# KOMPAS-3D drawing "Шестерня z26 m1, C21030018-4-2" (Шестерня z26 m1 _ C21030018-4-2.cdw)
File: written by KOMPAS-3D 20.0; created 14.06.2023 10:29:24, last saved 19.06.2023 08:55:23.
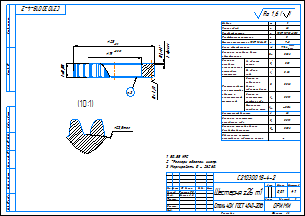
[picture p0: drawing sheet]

Sheet 1: A3, landscape

Document properties: Автор: user; Полное имя файла: C:\Users\kosenko.ky\Desktop\Чертежи\6 Июнь 2023\17. Шестерня z26 m1 _ C21030018-4-2\Шестерня z26 m1 _ C21030018-4-2.cdw; Знак неуказанной шероховатости: 4; Параметр неуказанной шероховатости: Ra 1,6; Масса: 0.00931038

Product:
- Part/product: Шестерня z26 m1  | designation C21030018-4-2
    Материал: Сталь 40Х  ГОСТ 4543-2016 (density 7850 kg/m3)
    Масса: 0.00931038
    source file: Шестерня z26 m1 _ C21030018-4-2.cdw

Title block, sheet 1: Наименование: Шестерня z26 m1; designation: C21030018-4-2; Материал: Сталь 40Х  ГОСТ 4543-2016; Масса: 0,01; Количество листов документа: 1; organisation: ОРИМИ; Форматы листов документа: A3; stored path: C:\Users\kosenko.ky\Desktop\Шестерня z26 m1 _ C21030018-4-2.cdw; Разработал: Косенко К.Ю.; Проверил: Михаль А.Д.
Table, sheet 1:
  669581292 / 683438702

Views: Проекционный вид 2, Местный разрез 1
Referenced files: mrsmyb.frw
Referenced files in C:\Users\kosenko.ky\Desktop\: Шестерня z26 m1 _ C21030018-4-2.m3d
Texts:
  Ячейка таблицы
  Ra 1,25
  Обозначение чертежа
  сопряжённого зубчатого колеса
  Допуск на торцовое биение
  базовой поверхности
  Допуск на погрешность
  направления зуба
  Делительный диаметр
  Контролировать
  при отсутствии
  обкатки с
  измерительной
  шестерней
  Допуск на
  колебание
  измерительного
  межосевого
  расстояния
  Допуск на колебание длины
  общей нормали
  Длина общей нормали
  Степень точности по ГОСТ 1643-81
  Коэффициент смещения
  Исходный контур
  Число зубьев
  Модуль
  Отклонение
  основного шага
  погрешность
  профиля зуба
  радиальное
  биение
  зубчатого венца
  На одном
  зубе
  За оборот
  колеса
  f Pt
  F vw
  ГОСТ 13755-2015
  Профиль зубьев
  Ra 1,6
  Ra 1,6 ( )
  gliv
  C21030018-4-2 Шестерня z26 m1
Dimensions and other numbers on the sheet: 1; 28; 19; 0,5; 4 фаски; 5±0,08; 0,006; 0,011; 26; 0,036; 0,02; 0,05; 0,022; 7,744 -0,055 -0,125; 7-C; 0; 23,5max; 3; 4:1; 0,01

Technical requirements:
  50...55 HRC
  *Размеры обеспеч. инстр.
  Маркировать ID - 26260.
